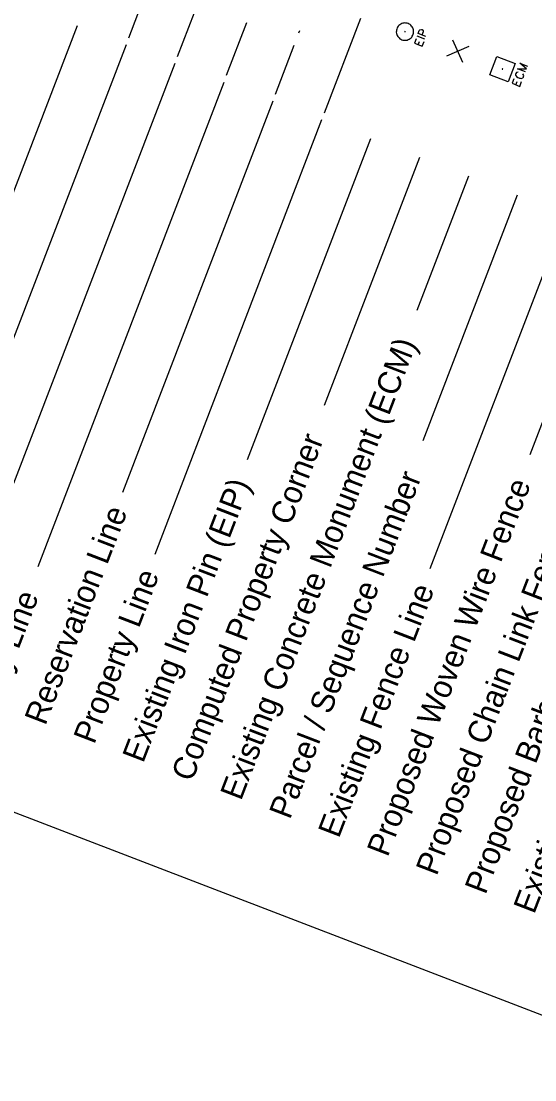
# Model space of a CAD drawing. Extents: x 1015221 to 1064345, y 619216 to 647967.
# Drawn here: x 1044921 to 1046459, y 624619 to 627789 of the extents above; entities that cross this region are included whole.
import ezdxf

# ---------------------------------------------------------------- set-up
doc = ezdxf.new("R2010")
doc.units = 0
doc.layers.add('Default', color=7, linetype='Continuous')
doc.layers.add('Sheet Symbology CELL', color=7, linetype='Continuous')

msp = doc.modelspace()

# ---------------------------------------------------------------- linework, layer by layer
at = {"layer": 'Default'}
for p, q in [((1045242.7, 627739.4), (1045292.1, 627868.2)), ((1045389.1, 627683.1), (1045439.9, 627815.3)), ((1045088.1, 627774.6), (1044553.5, 626383.1)), ((1045535.6, 627626.8), (1045596.5, 627785.3)), ((1045828.6, 627514.3), (1045937.6, 627798.1)), ((1045752.5, 627753.7), (1045755.3, 627761)), ((1046129.8, 627734.9), (1046106.3, 627743.9)), ((1045234.6, 627718.3), (1044714, 626363.4)), ((1045682.1, 627570.6), (1045738.4, 627717)), ((1046109.9, 627718.4), (1046113.6, 627728)), ((1046261.7, 627713.6), (1046194.7, 627683.8)), ((1046243.1, 627665.2), (1046213.3, 627732.2)), ((1045381, 627662.1), (1044897.9, 626404.5)), ((1045527.5, 627605.8), (1044970.2, 626155.1)), ((1046402.2, 627598.4), (1046405.9, 627608)), ((1045674, 627549.5), (1045223.6, 626377.1)), ((1045820.5, 627493.2), (1045320.6, 626192)), ((1045967, 627436.9), (1045597.5, 626475.4)), ((1046113.5, 627380.7), (1045828, 626637.7)), ((1046260, 627324.4), (1046105.7, 626922.8)), ((1046406.4, 627268.1), (1046123.7, 626532.1)), ((1046552.9, 627211.8), (1046144.6, 626149)), ((1046699.4, 627155.6), (1046443.8, 626490.2))]:
    msp.add_line(p, q, dxfattribs=at)
for points in [[(1046079.3, 627781.9), (1046076.1, 627782.9), (1046073, 627783.4), (1046069.7, 627783.6), (1046066.5, 627783.4), (1046063.3, 627782.6), (1046060.2, 627781.6), (1046057.3, 627780.3), (1046054.5, 627778.4), (1046052, 627776.5), (1046049.9, 627774), (1046048, 627771.3), (1046046.5, 627768.6), (1046045.3, 627765.4), (1046044.5, 627762.2), (1046044.2, 627759), (1046044.1, 627755.9), (1046044.6, 627752.5), (1046045.4, 627749.3), (1046046.7, 627746.4), (1046048.3, 627743.5), (1046050.2, 627741), (1046052.4, 627738.6), (1046055, 627736.5), (1046057.7, 627734.8), (1046060.7, 627733.4), (1046063.9, 627732.4), (1046067, 627731.9), (1046070.3, 627731.7), (1046073.6, 627732), (1046076.7, 627732.6), (1046079.8, 627733.7), (1046082.8, 627735), (1046085.5, 627736.8), (1046088.1, 627739), (1046090.1, 627741.3), (1046092, 627743.9), (1046093.6, 627746.9), (1046094.8, 627750), (1046095.5, 627753.1), (1046095.9, 627756.3), (1046096, 627759.6), (1046095.4, 627762.7), (1046094.7, 627765.9), (1046093.3, 627768.9), (1046091.7, 627771.7), (1046089.9, 627774.5), (1046087.6, 627776.7), (1046085.1, 627778.8), (1046082.4, 627780.5), (1046079.3, 627781.9)], [(1046069.6, 627758.3), (1046069.2, 627757.8), (1046069.4, 627757.3), (1046069.9, 627756.9), (1046070.5, 627757.1), (1046070.9, 627757.6), (1046070.7, 627758.2), (1046070.2, 627758.6), (1046069.6, 627758.3)], [(1046132.8, 627742.6), (1046109.3, 627751.6), (1046112.9, 627761), (1046114.9, 627763.4), (1046119.5, 627764.4), (1046121.7, 627763.6), (1046124.6, 627759.9), (1046124.4, 627756.6), (1046120.8, 627747.2)], [(1046103.4, 627736.3), (1046098.3, 627722.8), (1046121.7, 627713.8), (1046127.2, 627728.2)], [(1046324, 627628.6), (1046345.1, 627683.5), (1046399.9, 627662.4), (1046378.9, 627607.5), (1046324, 627628.6)], [(1046361.2, 627645.7), (1046361.4, 627645.3), (1046361.9, 627645.1), (1046362.7, 627645.4), (1046362.6, 627646.1), (1046362.2, 627646.5), (1046361.4, 627646.2), (1046361.2, 627645.7)], [(1046430.6, 627637), (1046407.2, 627646), (1046434, 627645.9), (1046413.8, 627663.4), (1046437.3, 627654.4)], [(1046395.8, 627616.3), (1046390.6, 627602.9), (1046414, 627593.8), (1046419.5, 627608.2)], [(1046408.9, 627636.7), (1046403.9, 627635.2), (1046402, 627632.6), (1046401.2, 627630.5), (1046400.9, 627627.5), (1046403.6, 627622.9), (1046408.4, 627620.1), (1046411.2, 627619.1), (1046413.1, 627618.4), (1046414.8, 627617.9), (1046418, 627617.3), (1046422.8, 627619), (1046424.7, 627621.5), (1046425.3, 627623.2), (1046425.8, 627626.6), (1046423.3, 627631.2)]]:
    msp.add_lwpolyline(points, dxfattribs=at)
at = {"layer": 'Sheet Symbology CELL'}
msp.add_lwpolyline([(1047783.5, 637166.9), (1043479.8, 625965.2), (1051313.4, 622955.5), (1055617.1, 634157.2)], close=True, dxfattribs=at)

# ---------------------------------------------------------------- texts
at = {"layer": 'Default'}
for s, height, p in [('Existing Concrete Monument (ECM)', 68.654, (1045578.8, 625452.2)), ('Computed Property Corner', 68.654, (1045432.3, 625508.5)), ('Parcel / Sequence Number', 68.654, (1045725.3, 625395.9)), ('Existing Iron Pin (EIP)', 68.654, (1045285.8, 625564.7)), ('Proposed Woven Wire Fence', 68.654, (1046018.2, 625283.4)), ('Reservation Line', 68.654, (1044992.8, 625677.3)), ('Proposed Barbed Wire Fence', 68.654, (1046311.2, 625170.8)), ('Proposed Chain Link Fence', 68.654, (1046164.7, 625227.1)), ('Existing Wetland Boundary', 68.654, (1046456.9, 625112.4)), ('Property Line', 68.654, (1045139.3, 625621)), ('Existing Fence Line', 68.654, (1045871.8, 625339.6)), ('City Line', 68.65, (1044846.4, 625733.6))]:
    msp.add_text(s, height=height, rotation=68.983, dxfattribs=at).set_placement(p)

doc.saveas('drawing.dxf')
